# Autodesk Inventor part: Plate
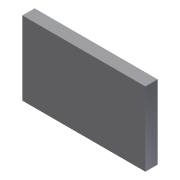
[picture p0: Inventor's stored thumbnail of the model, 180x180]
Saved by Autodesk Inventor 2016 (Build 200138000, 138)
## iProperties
Created: 2009-05
Part Number: Plate
Document SubType Name: Modeling
Designer: Sham
Density: 1 g/cm^3
Material: Generic
Appearance: Default
Author: Sham
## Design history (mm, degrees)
sketch "Sketch1"
  geometry: L1 (12.538, -14.287)-(-37.462, -14.288); L2 (-37.462, -14.288)-(-37.463, 15.712); L3 (-37.463, 15.712)-(12.537, 15.713); L4 (12.537, 15.713)-(12.538, -14.287)
  constraints: 8 end point, 2 parallel, 1 horizontal, 1 perpendicular
  dimensions: "d0" = 50 distance of L1.start L1.end; "d1" = 30 distance of L3.end L1.start
extrude "Extrusion1" new body sketch "Sketch1" distance "d2" = 5; taper "d3" = 0 deg
body "Solid1"
